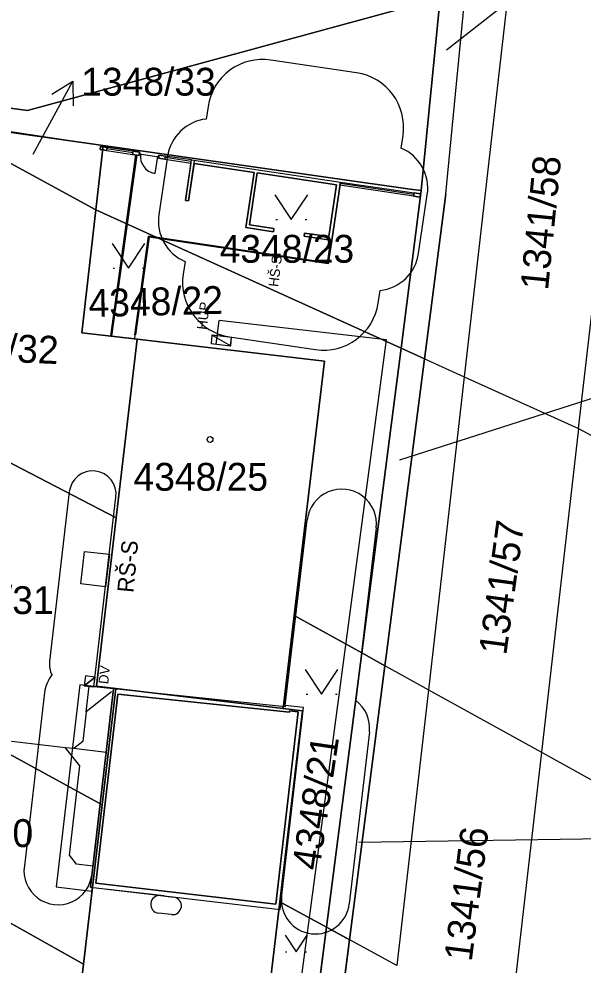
# Model space of a CAD drawing. Extents: x -735036 to -734743, y -1144813 to -1144181.
# Drawn here: x -734857.6 to -734823.1, y -1144559 to -1144501.3 of the extents above; entities that cross this region are included whole.
import ezdxf

# ---------------------------------------------------------------- set-up
doc = ezdxf.new("R2010")
doc.units = 0
for name, color, linetype in [('A3_Netisk', 7, 'Continuous'), ('A3_SIT_OBJEKTY_N01', 7, 'Continuous'), ('A3_SIT_PNB', 7, 'Continuous'), ('CKKOTY', 7, 'Continuous'), ('CKPLYN_POTRUBI_NT_PODZ_N', 7, 'Continuous'), ('CKTEXTY_MALE', 7, 'Continuous'), ('Katastr_HRANICE DRÁHY', 7, 'Continuous'), ('Katastr_Hranice parcel', 7, 'Continuous'), ('Katastr_Parcelní čísla', 7, 'Continuous'), ('Katastr_pozemek SŽDC_šrafy', 7, 'Continuous'), ('Katastr_pozemek_ČD_šrafy', 7, 'Continuous'), ('Katastr_Slučkované čáry', 7, 'Continuous'), ('Katastr_Značky kultur', 7, 'Continuous'), ('SO01_CKKANALIZACE_JEDNOTNA_PODZ_N', 7, 'Continuous'), ('ZÁBORY_dočasné', 7, 'Continuous'), ('ZÁBORY_dočasné_šrafy', 7, 'Continuous')]:
    doc.layers.add(name, color=color, linetype=linetype)

msp = doc.modelspace()

# ---------------------------------------------------------------- linework, layer by layer
msp.add_line((-734853.579, -1144541.96), (-734852.914, -1144541.433))
for points in [[(-734853.579, -1144541.96), (-734852.983, -1144542.029), (-734852.914, -1144541.433), (-734853.51, -1144541.364)], [(-734853.579, -1144541.96), (-734852.983, -1144542.029), (-734852.914, -1144541.433)]]:
    msp.add_lwpolyline(points, close=True)
at = {"layer": 'A3_Netisk'}
for p, q in [((-734838.465, -1144514.774), (-734837.936, -1144511.213)), ((-734851.783, -1144542.154), (-734853.2, -1144554.266)), ((-734848.694, -1144554.798), (-734852.306, -1144554.375))]:
    msp.add_line(p, q, dxfattribs=at)
msp.add_lwpolyline([(-734852.04, -1144533.939), (-734852.27, -1144535.925), (-734853.791, -1144535.749), (-734853.561, -1144533.763)], close=True, dxfattribs=at)
at = {"layer": 'A3_SIT_OBJEKTY_N01'}
for p, q in [((-734851.963, -1144520.613), (-734850.421, -1144509.56)), ((-734850.371, -1144509.567), (-734851.914, -1144520.619)), ((-734850.626, -1144509.529), (-734850.597, -1144509.332)), ((-734850.23, -1144509.588), (-734850.626, -1144509.529)), ((-734850.597, -1144509.332), (-734850.201, -1144509.39)), ((-734850.421, -1144509.56), (-734850.371, -1144509.567)), ((-734850.201, -1144509.39), (-734850.23, -1144509.588)), ((-734849.043, -1144509.765), (-734849.014, -1144509.567)), ((-734849.014, -1144509.567), (-734848.618, -1144509.626)), ((-734848.618, -1144509.626), (-734848.648, -1144509.823)), ((-734848.648, -1144509.823), (-734849.043, -1144509.765)), ((-734847.403, -1144512.334), (-734847.036, -1144509.861)), ((-734846.867, -1144510.088), (-734847.205, -1144512.363)), ((-734847.036, -1144509.861), (-734837.936, -1144511.213)), ((-734843.207, -1144510.632), (-734846.867, -1144510.088)), ((-734843.707, -1144513.995), (-734843.207, -1144510.632)), ((-734843.01, -1144510.661), (-734843.48, -1144513.826)), ((-734838.163, -1144511.381), (-734843.01, -1144510.661)), ((-734837.936, -1144511.213), (-734838.465, -1144514.774)), ((-734838.633, -1144514.546), (-734838.163, -1144511.381)), ((-734847.205, -1144512.363), (-734847.403, -1144512.334)), ((-734842.026, -1144514.245), (-734843.707, -1144513.995)), ((-734843.48, -1144513.826), (-734841.996, -1144514.047)), ((-734841.996, -1144514.047), (-734842.026, -1144514.245)), ((-734850.488, -1144520.532), (-734849.65, -1144514.527)), ((-734849.607, -1144514.584), (-734850.438, -1144520.538)), ((-734849.65, -1144514.527), (-734838.72, -1144516.151)), ((-734838.678, -1144516.208), (-734849.607, -1144514.584)), ((-734840.146, -1144514.524), (-734840.117, -1144514.326)), ((-734838.465, -1144514.774), (-734840.146, -1144514.524)), ((-734840.117, -1144514.326), (-734838.633, -1144514.546)), ((-734838.72, -1144516.151), (-734838.514, -1144514.766)), ((-734838.465, -1144514.774), (-734838.678, -1144516.208)), ((-734838.514, -1144514.766), (-734838.465, -1144514.774)), ((-734851.914, -1144520.619), (-734851.963, -1144520.613)), ((-734850.438, -1144520.538), (-734850.488, -1144520.532)), ((-734853.848, -1144541.911), (-734855.291, -1144554.247)), ((-734851.783, -1144542.154), (-734853.848, -1144541.911)), ((-734851.783, -1144542.154), (-734853.2, -1144554.27)), ((-734853.2, -1144554.27), (-734851.783, -1144542.154)), ((-734852.868, -1144554.007), (-734851.519, -1144542.484)), ((-734841.306, -1144543.249), (-734851.783, -1144542.154)), ((-734851.519, -1144542.484), (-734841.043, -1144543.578)), ((-734840.51, -1144543.563), (-734841.883, -1144555.293)), ((-734841.619, -1144555.625), (-734840.177, -1144543.299)), ((-734841.297, -1144543.168), (-734841.306, -1144543.249)), ((-734840.177, -1144543.299), (-734841.297, -1144543.168)), ((-734841.043, -1144543.578), (-734841.034, -1144543.501)), ((-734841.034, -1144543.501), (-734840.51, -1144543.563)), ((-734841.883, -1144555.293), (-734852.868, -1144554.007)), ((-734855.291, -1144554.247), (-734853.107, -1144554.503)), ((-734853.2, -1144554.27), (-734841.619, -1144555.625)), ((-734853.081, -1144554.284), (-734853.2, -1144554.27)), ((-734853.107, -1144554.503), (-734853.081, -1144554.284))]:
    msp.add_line(p, q, dxfattribs=at)
for points in [[(-734852.604, -1144509.236), (-734852.209, -1144509.294), (-734852.179, -1144509.097), (-734852.575, -1144509.038)], [(-734852.604, -1144509.236), (-734850.23, -1144509.588), (-734850.201, -1144509.39), (-734852.575, -1144509.038)], [(-734851.914, -1144520.619), (-734851.963, -1144520.613), (-734850.421, -1144509.56), (-734850.371, -1144509.567)], [(-734850.488, -1144520.532), (-734850.517, -1144520.781), (-734851.914, -1144520.619), (-734850.371, -1144509.567), (-734850.23, -1144509.588), (-734850.216, -1144509.489), (-734849.029, -1144509.666), (-734849.043, -1144509.765), (-734847.065, -1144510.059), (-734847.403, -1144512.334), (-734847.205, -1144512.363), (-734846.867, -1144510.088), (-734843.207, -1144510.632), (-734843.707, -1144513.995), (-734842.026, -1144514.245), (-734841.996, -1144514.047), (-734843.48, -1144513.826), (-734843.01, -1144510.661), (-734838.163, -1144511.381), (-734838.633, -1144514.546), (-734840.117, -1144514.326), (-734840.146, -1144514.524), (-734838.514, -1144514.766), (-734838.72, -1144516.151), (-734838.72, -1144516.151), (-734849.65, -1144514.527)], [(-734850.626, -1144509.529), (-734850.23, -1144509.588), (-734850.201, -1144509.39), (-734850.201, -1144509.39), (-734850.597, -1144509.332)], [(-734849.014, -1144509.567), (-734849.043, -1144509.765), (-734848.648, -1144509.823), (-734848.618, -1144509.626)], [(-734847.036, -1144509.861), (-734848.618, -1144509.626), (-734848.648, -1144509.823), (-734847.065, -1144510.059)], [(-734842.026, -1144514.245), (-734843.707, -1144513.995), (-734843.207, -1144510.632), (-734846.867, -1144510.088), (-734847.205, -1144512.363), (-734847.403, -1144512.334), (-734847.036, -1144509.861), (-734837.936, -1144511.213), (-734838.465, -1144514.774), (-734840.146, -1144514.524), (-734840.117, -1144514.326), (-734838.633, -1144514.546), (-734838.163, -1144511.381), (-734843.01, -1144510.661), (-734843.48, -1144513.826), (-734841.996, -1144514.047)], [(-734833.464, -1144512.079), (-734837.965, -1144511.411), (-734837.936, -1144511.213), (-734833.435, -1144511.881)], [(-734833.464, -1144512.079), (-734833.069, -1144512.138), (-734833.039, -1144511.94), (-734833.435, -1144511.881)], [(-734838.465, -1144514.774), (-734838.678, -1144516.208), (-734849.607, -1144514.584), (-734850.438, -1144520.538), (-734850.488, -1144520.532), (-734849.65, -1144514.527), (-734838.72, -1144516.151), (-734838.514, -1144514.766)], [(-734841.297, -1144543.168), (-734841.306, -1144543.249), (-734851.783, -1144542.154), (-734853.2, -1144554.27), (-734841.619, -1144555.625), (-734840.177, -1144543.299)], [(-734841.034, -1144543.501), (-734841.043, -1144543.578), (-734851.519, -1144542.484), (-734852.868, -1144554.007), (-734841.883, -1144555.293), (-734840.51, -1144543.563)]]:
    msp.add_lwpolyline(points, close=True, dxfattribs=at)
for points in [[(-734852.209, -1144509.294), (-734852.604, -1144509.236), (-734852.575, -1144509.038), (-734852.179, -1144509.097), (-734852.209, -1144509.294)], [(-734850.611, -1144509.431), (-734852.194, -1144509.195)], [(-734850.136, -1144509.501), (-734850.216, -1144509.489)], [(-734849.029, -1144509.666), (-734849.108, -1144509.654), (-734849.261, -1144510.683)], [(-734847.05, -1144509.96), (-734848.633, -1144509.724)], [(-734833.45, -1144511.98), (-734837.95, -1144511.312)], [(-734833.069, -1144512.138), (-734833.464, -1144512.079), (-734833.435, -1144511.881), (-734833.039, -1144511.94), (-734833.069, -1144512.138)], [(-734833.069, -1144512.138), (-734834.23, -1144521.36), (-734836.63, -1144539.96), (-734838.79, -1144556.7), (-734840.06, -1144566.59), (-734840.228, -1144567.714), (-734841.06, -1144574.32)]]:
    msp.add_lwpolyline(points, dxfattribs=at)
msp.add_arc((-734849.108, -1144509.654), 1.04, 171.54994, 261.54908, dxfattribs=at)
at = {"layer": 'A3_SIT_PNB'}
for points in [[(-734836.945, -1144504.546), (-734842.187, -1144503.767)], [(-734846.016, -1144506.605), (-734846.13, -1144507.371)], [(-734834.221, -1144509.14), (-734834.107, -1144508.375)], [(-734848.49, -1144509.645), (-734849.019, -1144513.206)], [(-734833.153, -1144515.563), (-734832.624, -1144512.002)], [(-734847.422, -1144516.067), (-734847.536, -1144516.833)], [(-734835.626, -1144518.602), (-734835.513, -1144517.837)], [(-734844.698, -1144520.662), (-734839.455, -1144521.44)], [(-734854.49, -1144530.117), (-734855.694, -1144540.487)], [(-734851.783, -1144542.154), (-734852.983, -1144542.029), (-734851.639, -1144530.45)], [(-734841.297, -1144543.168), (-734839.952, -1144531.834)], [(-734835.742, -1144532.333), (-734836.991, -1144542.861)], [(-734855.997, -1144542.375), (-734857.235, -1144552.957)], [(-734853.103, -1144553.441), (-734851.783, -1144542.154)], [(-734841.522, -1144554.796), (-734840.177, -1144543.299), (-734841.297, -1144543.168), (-734841.297, -1144543.168)], [(-734836.162, -1144544.775), (-734837.391, -1144555.279)], [(-734848.915, -1144554.772), (-734848.12, -1144554.865)], [(-734848.246, -1144555.937), (-734849.04, -1144555.844)]]:
    msp.add_lwpolyline(points, dxfattribs=at)
for centre, radius, start, end in [((-734842.683, -1144507.1), 3.37, 81.54908, 171.54908), ((-734837.44, -1144507.879), 3.37, 351.54908, 81.54908), ((-734845.834, -1144510.039), 2.685, 96.32984, 171.54908), ((-734835.28, -1144511.607), 2.685, 351.54908, 66.76833), ((-734846.363, -1144513.6), 2.685, 171.54908, 246.76833), ((-734835.809, -1144515.168), 2.685, 276.32984, 351.54908), ((-734844.202, -1144517.328), 3.37, 171.54908, 261.54908), ((-734838.96, -1144518.107), 3.37, 261.54908, 351.54908), ((-734853.064, -1144530.283), 1.435, 353.33341, 173.32709), ((-734837.847, -1144532.083), 2.12, 353.23643, 173.23644), ((-734854.268, -1144540.654), 1.435, 173.32808, 207.03421), ((-734853.931, -1144542.616), 2.08, 140.96329, 173.32599), ((-734838.227, -1144544.534), 2.08, 353.32599, 53.51095), ((-734855.176, -1144553.254), 2.081, 171.79921, 354.85276), ((-734848.977, -1144555.308), 0.54, 83.32837, 263.32599), ((-734848.977, -1144555.303), 0.535, 83.32351, 83.32831), ((-734848.183, -1144555.401), 0.54, 263.32927, 83.32599), ((-734839.457, -1144555.038), 2.08, 173.32599, 353.32599)]:
    msp.add_arc(centre, radius, start, end, dxfattribs=at)
at = {"layer": 'CKKOTY'}
msp.add_line((-734847.205, -1144512.363), (-734846.838, -1144509.89), dxfattribs=at)
at = {"layer": 'CKPLYN_POTRUBI_NT_PODZ_N'}
msp.add_line((-734845.514, -1144521.105), (-734845.346, -1144519.67), dxfattribs=at)
msp.add_lwpolyline([(-734840.638, -1144562.238), (-734835.108, -1144520.855), (-734845.346, -1144519.67)], dxfattribs=at)
for points in [[(-734844.641, -1144521.205), (-734844.583, -1144520.71), (-734845.775, -1144520.57), (-734845.833, -1144521.066)], [(-734844.633, -1144521.222), (-734844.583, -1144520.71), (-734845.773, -1144520.571)]]:
    msp.add_lwpolyline(points, close=True, dxfattribs=at)
at = {"layer": 'Katastr_HRANICE DRÁHY'}
for points in [[(-734832.95, -1144511.4), (-734831.84, -1144499.97)], [(-734834.23, -1144521.36), (-734832.99, -1144511.73)], [(-734832.99, -1144511.73), (-734832.95, -1144511.4)], [(-734836.63, -1144539.96), (-734834.23, -1144521.36)], [(-734838.79, -1144556.7), (-734836.63, -1144539.96)], [(-734840.06, -1144566.59), (-734838.79, -1144556.7)]]:
    msp.add_lwpolyline(points, dxfattribs=at)
at = {"layer": 'Katastr_Hranice parcel'}
for points in [[(-734852.42, -1144508.98), (-734862.79, -1144507.52)], [(-734852.87, -1144512.92), (-734862.79, -1144507.52)], [(-734852.87, -1144512.92), (-734852.42, -1144508.98)], [(-734852.42, -1144508.98), (-734833.68, -1144511.64)], [(-734832.99, -1144511.73), (-734833.68, -1144511.64)], [(-734853.72, -1144520.41), (-734852.87, -1144512.92)], [(-734850.22, -1144514.11), (-734852.87, -1144512.92)], [(-734850.22, -1144514.11), (-734834.23, -1144521.36)], [(-734850.35, -1144520.8), (-734853.72, -1144520.41)], [(-734850.35, -1144520.8), (-734851.62, -1144531.72)], [(-734838.91, -1144522.14), (-734850.35, -1144520.8)], [(-734834.23, -1144521.36), (-734830.38, -1144523.1)], [(-734840.76, -1144537.68), (-734838.91, -1144522.14)], [(-734830.38, -1144523.1), (-734823.4, -1144526.26)], [(-734864.73, -1144524.92), (-734851.62, -1144531.72)], [(-734823.4, -1144526.26), (-734818.94, -1144528.67)], [(-734851.62, -1144531.72), (-734852.82, -1144541.99)], [(-734841.43, -1144543.35), (-734840.76, -1144537.68)], [(-734840.76, -1144537.68), (-734836.63, -1144539.96)], [(-734836.63, -1144539.96), (-734832.56, -1144542.21)], [(-734852.48, -1144549.23), (-734866.58, -1144541.54)], [(-734852.82, -1144541.99), (-734851.65, -1144542.13)], [(-734851.65, -1144542.13), (-734852.48, -1144549.23)], [(-734851.65, -1144542.13), (-734841.43, -1144543.35)], [(-734832.56, -1144542.21), (-734825.66, -1144546.02)], [(-734841.63, -1144555.15), (-734840.25, -1144543.49)], [(-734841.43, -1144543.35), (-734840.25, -1144543.49)], [(-734825.66, -1144546.02), (-734821.17, -1144548.5)], [(-734852.48, -1144549.23), (-734853.62, -1144558.97)], [(-734853.62, -1144558.97), (-734867.65, -1144551.09)], [(-734842.81, -1144565.04), (-734841.63, -1144555.15)], [(-734838.79, -1144556.7), (-734841.63, -1144555.15)], [(-734834.48, -1144559.05), (-734838.79, -1144556.7)], [(-734853.62, -1144558.97), (-734854.52, -1144566.67)]]:
    msp.add_lwpolyline(points, dxfattribs=at)
at = {"layer": 'Katastr_Parcelní čísla'}
for p, q in [((-734855.563, -1144505.849), (-734854.284, -1144505.063)), ((-734856.7, -1144509.52), (-734856.19, -1144508.58))]:
    msp.add_line(p, q, dxfattribs=at)
msp.add_lwpolyline([(-734856.19, -1144508.58), (-734854.284, -1144505.063), (-734854.244, -1144506.563)], dxfattribs=at)
at = {"layer": 'Katastr_pozemek SŽDC_šrafy'}
for points in [[(-734850.35, -1144520.8), (-734853.72, -1144520.41), (-734852.87, -1144512.92), (-734862.79, -1144507.52), (-734864.73, -1144524.92), (-734851.62, -1144531.72), (-734850.35, -1144520.8)], [(-734852.42, -1144508.98), (-734862.79, -1144507.52), (-734852.87, -1144512.92), (-734852.42, -1144508.98)], [(-734832.99, -1144511.73), (-734833.68, -1144511.64), (-734852.42, -1144508.98), (-734852.87, -1144512.92), (-734850.22, -1144514.11), (-734834.23, -1144521.36), (-734832.99, -1144511.73)], [(-734834.23, -1144521.36), (-734850.22, -1144514.11), (-734852.87, -1144512.92), (-734853.72, -1144520.41), (-734850.35, -1144520.8), (-734838.91, -1144522.14), (-734840.76, -1144537.68), (-734836.63, -1144539.96), (-734834.23, -1144521.36)], [(-734838.91, -1144522.14), (-734850.35, -1144520.8), (-734851.62, -1144531.72), (-734852.82, -1144541.99), (-734851.65, -1144542.13), (-734841.43, -1144543.35), (-734840.76, -1144537.68), (-734838.91, -1144522.14)], [(-734851.62, -1144531.72), (-734864.73, -1144524.92), (-734866.58, -1144541.54), (-734852.48, -1144549.23), (-734851.65, -1144542.13), (-734852.82, -1144541.99), (-734851.62, -1144531.72)], [(-734836.63, -1144539.96), (-734840.76, -1144537.68), (-734841.43, -1144543.35), (-734840.25, -1144543.49), (-734841.63, -1144555.15), (-734838.79, -1144556.7), (-734836.63, -1144539.96)], [(-734852.48, -1144549.23), (-734866.58, -1144541.54), (-734867.65, -1144551.09), (-734853.62, -1144558.97), (-734852.48, -1144549.23)], [(-734841.63, -1144555.15), (-734840.25, -1144543.49), (-734841.43, -1144543.35), (-734851.65, -1144542.13), (-734852.48, -1144549.23), (-734853.62, -1144558.97), (-734854.52, -1144566.67), (-734843.73, -1144572.8), (-734842.81, -1144565.04), (-734841.63, -1144555.15)], [(-734867.65, -1144551.09), (-734868.04, -1144554.63), (-734872.67, -1144556.37), (-734854.52, -1144566.67), (-734853.62, -1144558.97), (-734867.65, -1144551.09)], [(-734838.79, -1144556.7), (-734841.63, -1144555.15), (-734842.81, -1144565.04), (-734840.06, -1144566.59), (-734838.79, -1144556.7)]]:
    msp.add_lwpolyline(points, dxfattribs=at)
at = {"layer": 'Katastr_pozemek_ČD_šrafy'}
msp.add_lwpolyline([(-734850.16, -1144494.56), (-734850.37, -1144495.22), (-734851.22, -1144494.96), (-734851.02, -1144494.29), (-734876.91, -1144486.38), (-734880.187, -1144499.973), (-734865.5, -1144507.03), (-734862.79, -1144507.52), (-734852.42, -1144508.98), (-734833.68, -1144511.64), (-734832.99, -1144511.73), (-734832.95, -1144511.4), (-734831.84, -1144499.97), (-734850.16, -1144494.56)], dxfattribs=at)
at = {"layer": 'Katastr_Slučkované čáry'}
for points in [[(-734826.61, -1144490.15), (-734830.38, -1144523.1)], [(-734823.4, -1144526.26), (-734819.59, -1144493.44)], [(-734830.38, -1144523.1), (-734832.56, -1144542.21)], [(-734823.4, -1144526.26), (-734825.66, -1144546.02)], [(-734832.56, -1144542.21), (-734834.48, -1144559.05)], [(-734825.66, -1144546.02), (-734827.58, -1144562.82)]]:
    msp.add_lwpolyline(points, dxfattribs=at)
at = {"layer": 'Katastr_Značky kultur'}
for p, q in [((-734841.88, -1144513.5), (-734841.78, -1144513.5)), ((-734840.08, -1144513.5), (-734839.98, -1144513.5)), ((-734851.82, -1144516.47), (-734851.72, -1144516.47)), ((-734850.02, -1144516.47), (-734849.92, -1144516.47)), ((-734840.03, -1144542.48), (-734839.93, -1144542.48)), ((-734838.23, -1144542.48), (-734838.13, -1144542.48)), ((-734841.31, -1144557.195), (-734840.64, -1144558.2)), ((-734840.64, -1144558.2), (-734839.97, -1144557.195)), ((-734841.277, -1144558.2), (-734841.21, -1144558.2)), ((-734840.071, -1144558.2), (-734840.003, -1144558.2))]:
    msp.add_line(p, q, dxfattribs=at)
for points in [[(-734841.93, -1144512), (-734840.93, -1144513.5), (-734839.93, -1144512)], [(-734851.87, -1144514.97), (-734850.87, -1144516.47), (-734849.87, -1144514.97)], [(-734840.08, -1144540.98), (-734839.08, -1144542.48), (-734838.08, -1144540.98)]]:
    msp.add_lwpolyline(points, dxfattribs=at)
msp.add_circle((-734845.89, -1144526.93), 0.175, dxfattribs=at)
at = {"layer": 'SO01_CKKANALIZACE_JEDNOTNA_PODZ_N'}
msp.add_line((-734853.457, -1144543.555), (-734853.276, -1144541.995), dxfattribs=at)
for points in [[(-734851.904, -1144542.327), (-734853.457, -1144543.555), (-734853.669, -1144545.365), (-734854.223, -1144545.804)], [(-734852.237, -1144546.036), (-734854.223, -1144545.804), (-734854.72, -1144545.746), (-734865.823, -1144544.448), (-734866.393, -1144544.885)], [(-734853.049, -1144552.979), (-734854.043, -1144552.863), (-734854.481, -1144552.308), (-734853.843, -1144546.855), (-734854.72, -1144545.746)]]:
    msp.add_lwpolyline(points, dxfattribs=at)
at = {"layer": 'ZÁBORY_dočasné'}
for p, q in [((-734810.273, -1144486.527), (-734831.445, -1144503.169)), ((-734857.053, -1144506.856), (-734831.84, -1144499.97)), ((-734831.84, -1144499.97), (-734832.99, -1144511.73)), ((-734869.357, -1144505.177), (-734857.053, -1144506.856)), ((-734865.5, -1144507.03), (-734852.42, -1144508.98)), ((-734852.42, -1144508.98), (-734832.99, -1144511.73)), ((-734832.99, -1144511.73), (-734834.23, -1144521.36)), ((-734834.299, -1144528.172), (-734807.068, -1144519.455)), ((-734836.63, -1144539.96), (-734834.23, -1144521.36)), ((-734834.23, -1144521.36), (-734832.801, -1144522.006)), ((-734836.63, -1144539.96), (-734838.79, -1144556.7)), ((-734835.218, -1144540.74), (-734836.63, -1144539.96)), ((-734788.003, -1144550.788), (-734836.806, -1144551.531)), ((-734838.79, -1144556.7), (-734840.06, -1144566.59)), ((-734838.79, -1144556.7), (-734837.377, -1144557.471)), ((-734837.377, -1144557.471), (-734838.649, -1144567.383))]:
    msp.add_line(p, q, dxfattribs=at)
for points in [[(-734831.496, -1144511.942), (-734830.375, -1144500.403)], [(-734831.496, -1144511.942), (-734832.742, -1144521.55), (-734832.801, -1144522.006)], [(-734832.801, -1144522.006), (-734832.801, -1144522.006), (-734835.142, -1144540.152), (-734835.218, -1144540.74)], [(-734835.218, -1144540.74), (-734835.218, -1144540.74), (-734835.218, -1144540.74), (-734837.377, -1144557.471), (-734837.377, -1144557.471)]]:
    msp.add_lwpolyline(points, dxfattribs=at)
at = {"layer": 'ZÁBORY_dočasné_šrafy'}
for points in [[(-734857.053, -1144506.856), (-734869.357, -1144505.177), (-734865.5, -1144507.03), (-734852.42, -1144508.98), (-734832.99, -1144511.73), (-734831.84, -1144499.97), (-734857.053, -1144506.856)], [(-734830.375, -1144500.403), (-734831.84, -1144499.97), (-734832.99, -1144511.73), (-734834.23, -1144521.36), (-734832.801, -1144522.006), (-734832.742, -1144521.55), (-734831.496, -1144511.942), (-734830.375, -1144500.403)], [(-734832.801, -1144522.006), (-734834.23, -1144521.36), (-734836.63, -1144539.96), (-734835.218, -1144540.74), (-734835.142, -1144540.152), (-734832.801, -1144522.006)], [(-734835.218, -1144540.74), (-734836.63, -1144539.959), (-734838.79, -1144556.699), (-734837.377, -1144557.47), (-734835.218, -1144540.74)], [(-734837.377, -1144557.47), (-734838.79, -1144556.699), (-734840.06, -1144566.589), (-734838.649, -1144567.382), (-734837.377, -1144557.47)]]:
    msp.add_lwpolyline(points, dxfattribs=at)

# ---------------------------------------------------------------- texts
at = {"layer": 'A3_Netisk'}
msp.add_text('RŠ-S', height=1, rotation=84.74142, dxfattribs=at).set_placement((-734850.57, -1144536.314))
at = {"layer": 'CKTEXTY_MALE'}
for s, p in [('HŠ-S', (-734841.727, -1144517.637)), ('HUP', (-734846.102, -1144520.255)), ('DV', (-734852.12, -1144541.888))]:
    msp.add_text(s, height=0.6, rotation=83.326, dxfattribs=at).set_placement(p)
at = {"layer": 'Katastr_Parcelní čísla'}
for s, p in [('1348/33', (-734853.76, -1144505.94)), ('4348/23', (-734845.307, -1144516.14)), ('4348/25', (-734850.567, -1144530.06)), ('1348/31', (-734863.663, -1144537.59)), ('1348/30', (-734864.914, -1144551.81))]:
    msp.add_text(s, height=1.7, dxfattribs=at).set_placement(p)
for s, rotation, p in [('1341/58', 84.32748, (-734825.254, -1144517.864)), ('4348/22', 1.45107, (-734853.296, -1144519.463)), ('1348/32', 357.57765, (-734863.39, -1144521.981)), ('1341/57', 82.29411, (-734827.803, -1144540.14)), ('4348/21', 81.57303, (-734839.215, -1144553.287)), ('1341/56', 82.69425, (-734829.917, -1144558.849))]:
    msp.add_text(s, height=1.7, rotation=rotation, dxfattribs=at).set_placement(p)

doc.saveas('drawing.dxf')
